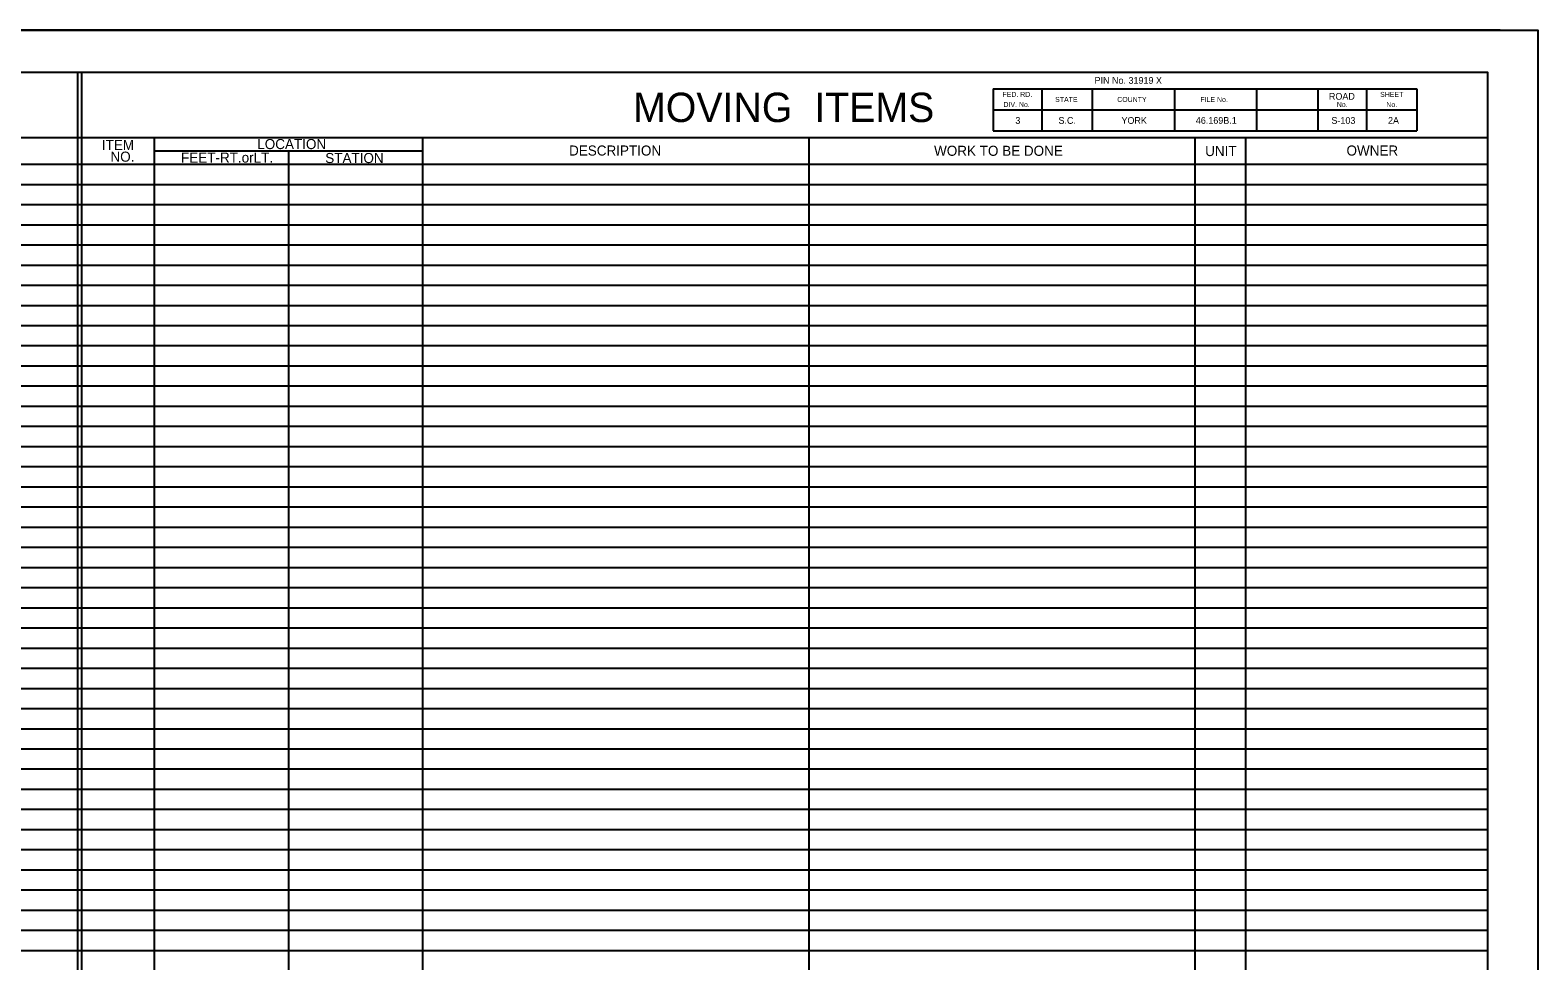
# Model space of a CAD drawing. Extents: x 8134 to 11793, y 3225 to 13425.
# Drawn here: x 10884 to 11782, y 7171 to 7725 of the extents above; entities that cross this region are included whole.
import ezdxf

# ---------------------------------------------------------------- set-up
doc = ezdxf.new("R2010")
doc.units = 0
for name, color, linetype in [('RD_SHT_Bndy', 7, 'Continuous'), ('RD_SHT_IplotShp', 7, 'Continuous'), ('RD_SHT_TX', 7, 'Continuous')]:
    doc.layers.add(name, color=color, linetype=linetype)

msp = doc.modelspace()

# ---------------------------------------------------------------- linework, layer by layer
at = {"layer": 'RD_SHT_Bndy'}
for p, q in [((10000, 7725), (11760, 7725)), ((11760, 7725), (10000, 7725)), ((10912.65, 7700), (10912.65, 6650)), ((10915.15, 7700), (10915.15, 6650)), ((11457.95, 7690), (11457.95, 7665)), ((11457.95, 7690), (11710.45, 7690)), ((11486.95, 7690), (11486.95, 7677.5)), ((11516.95, 7690), (11516.95, 7677.5)), ((11565.95, 7690), (11565.95, 7677.5)), ((11614.95, 7690), (11614.95, 7677.5)), ((11651.45, 7690), (11651.45, 7677.5)), ((11680.45, 7690), (11680.45, 7677.5)), ((11710.45, 7690), (11710.45, 7665)), ((11457.95, 7677.5), (11710.45, 7677.5)), ((11486.95, 7677.5), (11486.95, 7665)), ((11516.95, 7677.5), (11516.95, 7665)), ((11565.95, 7677.5), (11565.95, 7665)), ((11614.95, 7677.5), (11614.95, 7665)), ((11651.45, 7677.5), (11651.45, 7665)), ((11680.45, 7677.5), (11680.45, 7665)), ((11752.45, 7661), (10077.45, 7661)), ((10958.45, 6650), (10958.45, 7661)), ((11118.45, 6650), (11118.45, 7661)), ((11348.45, 6650), (11348.45, 7661)), ((11457.95, 7665), (11710.45, 7665)), ((11578.45, 6650), (11578.45, 7661)), ((11608.45, 6650), (11608.45, 7661)), ((11118.45, 7653), (10958.45, 7653)), ((11038.45, 6650), (11038.45, 7653)), ((11752.45, 7645), (10077.45, 7645)), ((11752.45, 7633), (10077.45, 7633)), ((11752.45, 7621), (10077.45, 7621)), ((11752.45, 7609), (10077.45, 7609)), ((11752.45, 7597), (10077.45, 7597)), ((11752.45, 7585), (10077.45, 7585)), ((11752.45, 7573), (10077.45, 7573)), ((11752.45, 7561), (10077.45, 7561)), ((11752.45, 7549), (10077.45, 7549)), ((11752.45, 7537), (10077.45, 7537)), ((11752.45, 7525), (10077.45, 7525)), ((11752.45, 7513), (10077.45, 7513)), ((11752.45, 7501), (10077.45, 7501)), ((11752.45, 7489), (10077.45, 7489)), ((11752.45, 7477), (10077.45, 7477)), ((11752.45, 7465), (10077.45, 7465)), ((11752.45, 7453), (10077.45, 7453)), ((11752.45, 7441), (10077.45, 7441)), ((11752.45, 7429), (10077.45, 7429)), ((11752.45, 7417), (10077.45, 7417)), ((11752.45, 7405), (10077.45, 7405)), ((11752.45, 7393), (10077.45, 7393)), ((11752.45, 7381), (10077.45, 7381)), ((11752.45, 7369), (10077.45, 7369)), ((11752.45, 7357), (10077.45, 7357)), ((11752.45, 7345), (10077.45, 7345)), ((11752.45, 7333), (10077.45, 7333)), ((11752.45, 7321), (10077.45, 7321)), ((11752.45, 7309), (10077.45, 7309)), ((11752.45, 7297), (10077.45, 7297)), ((11752.45, 7285), (10077.45, 7285)), ((11752.45, 7273), (10077.45, 7273)), ((11752.45, 7261), (10077.45, 7261)), ((11752.45, 7249), (10077.45, 7249)), ((11752.45, 7237), (10077.45, 7237)), ((11752.45, 7225), (10077.45, 7225)), ((11752.45, 7213), (10077.45, 7213)), ((11752.45, 7201), (10077.45, 7201)), ((11752.45, 7189), (10077.45, 7189)), ((11752.45, 7177), (10077.45, 7177))]:
    msp.add_line(p, q, dxfattribs=at)
msp.add_lwpolyline([(10077.45, 7700), (11752.45, 7700), (11752.45, 6650), (10077.45, 6650)], close=True, dxfattribs=at)
at = {"layer": 'RD_SHT_IplotShp'}
msp.add_lwpolyline([(9986.5, 7725), (11782.45, 7725), (11782.45, 6625), (9986.5, 6625)], close=True, dxfattribs=at)

# ---------------------------------------------------------------- texts
at = {"layer": 'RD_SHT_TX'}
for s, height, p in [('PIN No. 31919 X   ', 4, (11518.42, 7693.09)), ('MOVING  ITEMS', 17.4999, (11243.55, 7670.3)), ('FED. RD.', 3, (11463.57, 7685.25)), ('      ROAD      ', 4, (11649.09, 7683.6)), ('SHEET', 3, (11688.53, 7685.25)), ('DIV. No.', 3, (11464.19, 7679.25)), ('STATE', 3, (11494.97, 7682.25)), ('COUNTY', 3, (11531.94, 7682.25)), ('FILE No.', 3, (11581.45, 7682.25)), ('No.', 3, (11662.71, 7679.25)), ('No.', 3, (11692.21, 7679.25)), ('3', 4, (11471.25, 7669.25)), ('S.C.', 4, (11496.93, 7669.25)), ('      YORK      ', 4, (11525.53, 7669.25)), ('   46.169B.1    ', 4, (11574.29, 7669.25)), ('     S-103      ', 4, (11652.07, 7669.25)), ('       2A       ', 4, (11682.8, 7669.25)), ('LOCATION', 6, (11019.75, 7654.2)), ('ITEM', 6, (10927.2, 7653.65)), ('NO.', 6, (10932.3, 7646.7)), ('FEET-RT.orLT.', 6, (10974.35, 7646.15)), ('STATION', 6, (11060.25, 7645.9)), ('DESCRIPTION', 6, (11205.45, 7650.35)), ('WORK TO BE DONE', 6, (11422.85, 7650.2)), ('UNIT', 6, (11584.3, 7650.05)), ('OWNER', 6, (11668.5, 7650.35))]:
    msp.add_text(s, height=height, dxfattribs=at).set_placement(p)

doc.saveas('drawing.dxf')
